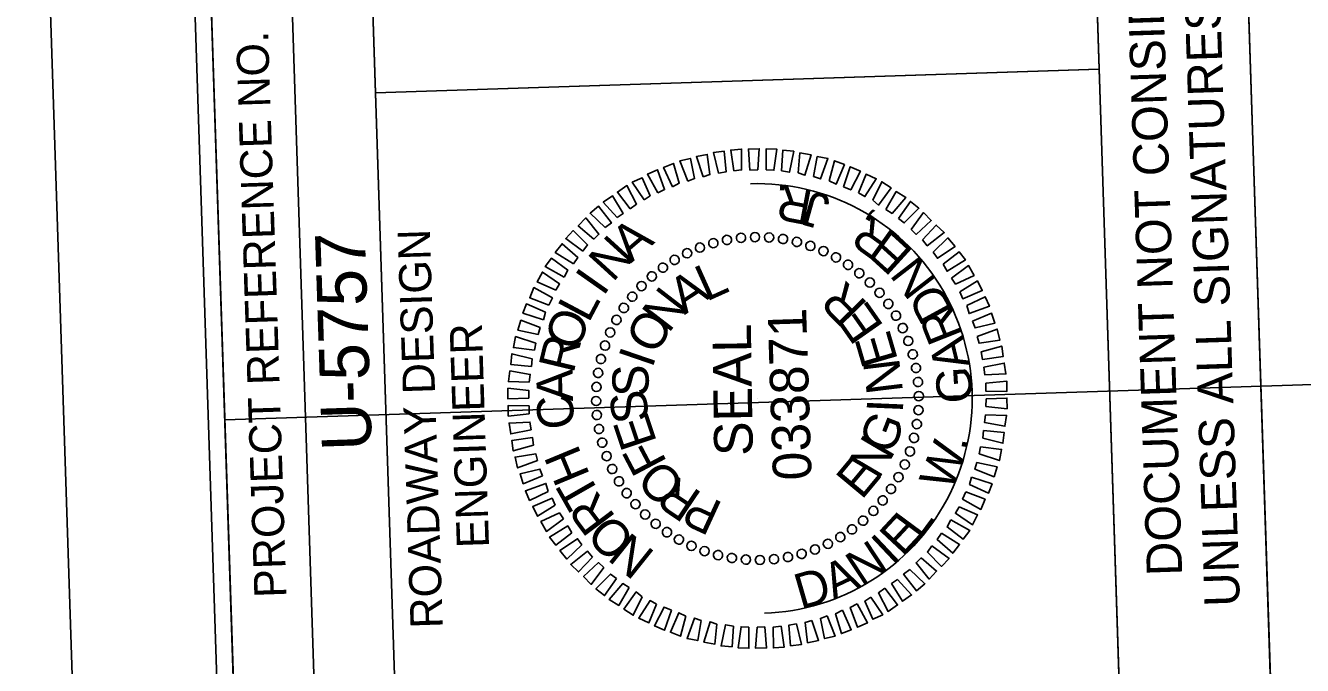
# Model space of a CAD drawing. Extents: x 1627314 to 1628469, y 762309 to 764212.
# Drawn here: x 1627314.2 to 1627512.6, y 763788.2 to 763887.6 of the extents above; entities that cross this region are included whole.
import ezdxf

# ---------------------------------------------------------------- set-up
doc = ezdxf.new("R2010")
doc.units = 0
for name, color, linetype in [('Old_Level_58', 7, 'Continuous'), ('Scratch_Level_0', 7, 'Continuous'), ('Sheet Data Field CELL', 7, 'Continuous'), ('Sheet Layout Profile Border Port 1', 7, 'Continuous'), ('Sheet Plot Border Inside CELL', 7, 'Continuous'), ('Sheet Plot Border Outside CELL', 7, 'Continuous'), ('Sheet Professional Seal CELL', 7, 'Continuous'), ('Sheet Profile CELL', 7, 'Continuous'), ('Sheet Profile Grid Major CELL', 7, 'Continuous'), ('Sheet Profile Grid Minor CELL', 7, 'Continuous'), ('Sheet Sticker Exception Certification CELL', 7, 'Continuous')]:
    doc.layers.add(name, color=color, linetype=linetype)

msp = doc.modelspace()

# ---------------------------------------------------------------- linework, layer by layer
at = {"layer": 'Old_Level_58'}
msp.add_lwpolyline([(1627507.79, 763781.55), (1627501.25, 763981.49), (1627565.16, 763983.58), (1627571.7, 763783.64)], close=True, dxfattribs=at)
at = {"layer": 'Scratch_Level_0'}
msp.add_arc((1627427.94, 763829.65), 33.36, 271.8735, 91.8735, dxfattribs=at)
at = {"layer": 'Sheet Layout Profile Border Port 1'}
msp.add_lwpolyline([(1627386.05, 762576.99), (1627885.78, 762593.33), (1627841.65, 763942.61), (1627566.8, 763933.62), (1627570.07, 763833.63), (1627345.19, 763826.32)], close=True, dxfattribs=at)
at = {"layer": 'Sheet Plot Border Inside CELL'}
msp.add_lwpolyline([(1628446.34, 762357.53), (1628391.86, 764023.14), (1627337.33, 763988.65), (1627391.81, 762323.04)], close=True, dxfattribs=at)
at = {"layer": 'Sheet Plot Border Outside CELL'}
msp.add_lwpolyline([(1628469.21, 762345.27), (1628413.63, 764044.37), (1627314.22, 764008.4), (1627369.79, 762309.31)], close=True, dxfattribs=at)
at = {"layer": 'Sheet Professional Seal CELL'}
for p, q in [((1627423.24, 763854.26), (1627423.24, 763854.26)), ((1627425.37, 763854.63), (1627425.37, 763854.63)), ((1627427.57, 763854.75), (1627427.57, 763854.75)), ((1627429.78, 763854.67), (1627429.78, 763854.67)), ((1627431.94, 763854.39), (1627431.94, 763854.39)), ((1627417, 763852.25), (1627417, 763852.25)), ((1627418.97, 763853.12), (1627418.97, 763853.12)), ((1627421.05, 763853.78), (1627421.05, 763853.78)), ((1627434.05, 763854.01), (1627434.05, 763854.01)), ((1627436.17, 763853.38), (1627436.17, 763853.38)), ((1627438.2, 763852.54), (1627438.2, 763852.54)), ((1627415.08, 763851.19), (1627415.08, 763851.19)), ((1627440.18, 763851.61), (1627440.18, 763851.61)), ((1627442.02, 763850.42), (1627442.02, 763850.42)), ((1627411.51, 763848.67), (1627411.51, 763848.67)), ((1627413.22, 763849.98), (1627413.22, 763849.98)), ((1627443.81, 763849.13), (1627443.81, 763849.13)), ((1627409.91, 763847.12), (1627409.91, 763847.12)), ((1627445.41, 763847.68), (1627445.41, 763847.68)), ((1627408.46, 763845.52), (1627408.46, 763845.52)), ((1627446.97, 763846.08), (1627446.97, 763846.08)), ((1627448.27, 763844.37), (1627448.27, 763844.37)), ((1627407.17, 763843.73), (1627407.17, 763843.73)), ((1627449.48, 763842.51), (1627449.48, 763842.51)), ((1627405.98, 763841.89), (1627405.98, 763841.89)), ((1627450.55, 763840.59), (1627450.55, 763840.59)), ((1627405.05, 763839.9), (1627405.05, 763839.9)), ((1627451.41, 763838.62), (1627451.41, 763838.62)), ((1627404.21, 763837.88), (1627404.21, 763837.88)), ((1627452.08, 763836.54), (1627452.08, 763836.54)), ((1627403.58, 763835.75), (1627403.58, 763835.75)), ((1627403.2, 763833.64), (1627403.2, 763833.64)), ((1627452.55, 763834.35), (1627452.55, 763834.35)), ((1627402.92, 763831.48), (1627402.92, 763831.48)), ((1627452.92, 763832.22), (1627452.92, 763832.22)), ((1627402.84, 763829.28), (1627402.84, 763829.28)), ((1627427.94, 763829.65), (1627427.94, 763829.65)), ((1627453.04, 763830.02), (1627453.04, 763830.02)), ((1627402.96, 763827.08), (1627402.96, 763827.08)), ((1627452.97, 763827.81), (1627452.97, 763827.81)), ((1627403.33, 763824.94), (1627403.33, 763824.94)), ((1627452.69, 763825.65), (1627452.69, 763825.65)), ((1627403.81, 763822.75), (1627403.81, 763822.75)), ((1627452.31, 763823.54), (1627452.31, 763823.54)), ((1627404.47, 763820.68), (1627404.47, 763820.68)), ((1627451.67, 763821.42), (1627451.67, 763821.42)), ((1627405.34, 763818.7), (1627405.34, 763818.7)), ((1627450.84, 763819.39), (1627450.84, 763819.39)), ((1627406.4, 763816.79), (1627406.4, 763816.79)), ((1627449.9, 763817.41), (1627449.9, 763817.41)), ((1627407.61, 763814.92), (1627407.61, 763814.92)), ((1627448.71, 763815.57), (1627448.71, 763815.57)), ((1627408.92, 763813.22), (1627408.92, 763813.22)), ((1627447.42, 763813.78), (1627447.42, 763813.78)), ((1627410.47, 763811.62), (1627410.47, 763811.62)), ((1627444.37, 763810.62), (1627444.37, 763810.62)), ((1627445.97, 763812.18), (1627445.97, 763812.18)), ((1627412.07, 763810.17), (1627412.07, 763810.17)), ((1627413.86, 763808.88), (1627413.86, 763808.88)), ((1627442.67, 763809.32), (1627442.67, 763809.32)), ((1627415.7, 763807.69), (1627415.7, 763807.69)), ((1627417.69, 763806.75), (1627417.69, 763806.75)), ((1627438.89, 763807.04), (1627438.89, 763807.04)), ((1627440.8, 763808.11), (1627440.8, 763808.11)), ((1627419.71, 763805.92), (1627419.71, 763805.92)), ((1627421.84, 763805.28), (1627421.84, 763805.28)), ((1627423.95, 763804.9), (1627423.95, 763804.9)), ((1627426.11, 763804.62), (1627426.11, 763804.62)), ((1627430.51, 763804.67), (1627430.51, 763804.67)), ((1627432.65, 763805.04), (1627432.65, 763805.04)), ((1627434.84, 763805.51), (1627434.84, 763805.51)), ((1627436.91, 763806.18), (1627436.91, 763806.18)), ((1627428.31, 763804.55), (1627428.31, 763804.55))]:
    msp.add_line(p, q, dxfattribs=at)
for points in [[(1627424.29, 763865), (1627423.78, 763868.23), (1627425.48, 763868.39), (1627425.48, 763865.14)], [(1627426.78, 763865.13), (1627426.53, 763868.37), (1627428.23, 763868.43), (1627427.98, 763865.17)], [(1627429.28, 763865.16), (1627429.28, 763868.41), (1627430.93, 763868.37), (1627430.49, 763865.1)], [(1627431.69, 763864.99), (1627431.88, 763868.2), (1627433.59, 763868.05), (1627432.9, 763864.78)], [(1627414.76, 763862.53), (1627413.36, 763865.54), (1627414.89, 763866.14), (1627415.79, 763863.07)], [(1627417.13, 763863.41), (1627415.88, 763866.57), (1627417.52, 763866.93), (1627418.17, 763863.8)], [(1627419.51, 763864.09), (1627418.46, 763867.21), (1627420.15, 763867.56), (1627420.55, 763864.42)], [(1627421.9, 763864.62), (1627421.09, 763867.84), (1627422.78, 763868.05), (1627423.09, 763864.86)], [(1627434.25, 763864.67), (1627434.55, 763867.78), (1627436.26, 763867.49), (1627435.31, 763864.31)], [(1627436.67, 763864.1), (1627437.22, 763867.22), (1627438.88, 763866.92), (1627437.73, 763863.74)], [(1627439.09, 763863.43), (1627439.89, 763866.56), (1627441.46, 763865.96), (1627440.16, 763862.91)], [(1627412.44, 763861.56), (1627410.85, 763864.46), (1627412.42, 763865.16), (1627413.52, 763862.09)], [(1627441.33, 763862.5), (1627442.37, 763865.64), (1627443.95, 763864.94), (1627442.44, 763862.04)], [(1627443.66, 763861.58), (1627444.81, 763864.47), (1627446.39, 763863.77), (1627444.63, 763861.01)], [(1627408.17, 763859.12), (1627406.18, 763861.7), (1627407.65, 763862.7), (1627409.15, 763859.85)], [(1627410.33, 763860.49), (1627408.48, 763863.23), (1627410.01, 763863.93), (1627411.26, 763861.12)], [(1627445.85, 763860.45), (1627447.25, 763863.3), (1627448.69, 763862.34), (1627446.77, 763859.68)], [(1627406.16, 763857.75), (1627403.98, 763860.13), (1627405.4, 763861.13), (1627407.09, 763858.38)], [(1627447.89, 763859.02), (1627449.5, 763861.77), (1627450.98, 763860.87), (1627448.86, 763858.4)], [(1627449.84, 763857.58), (1627451.71, 763860.24), (1627453.04, 763859.18), (1627450.76, 763856.91)], [(1627404.26, 763856.19), (1627401.94, 763858.41), (1627403.25, 763859.51), (1627405.24, 763856.92)], [(1627451.8, 763855.89), (1627453.76, 763858.51), (1627454.95, 763857.29), (1627452.62, 763855.12)], [(1627402.52, 763854.38), (1627400.1, 763856.45), (1627401.26, 763857.69), (1627403.3, 763855.16)], [(1627453.6, 763854.3), (1627455.73, 763856.57), (1627456.97, 763855.41), (1627454.33, 763853.37)], [(1627400.83, 763852.52), (1627398.16, 763854.49), (1627399.32, 763855.73), (1627401.55, 763853.5)], [(1627455.22, 763852.35), (1627457.54, 763854.58), (1627458.64, 763853.26), (1627455.9, 763851.42)], [(1627399.34, 763850.57), (1627396.53, 763852.33), (1627397.59, 763853.67), (1627400.01, 763851.55)], [(1627456.78, 763850.5), (1627459.26, 763852.43), (1627460.26, 763851.17), (1627457.41, 763849.42)], [(1627397.91, 763848.48), (1627394.96, 763850.13), (1627395.96, 763851.46), (1627398.47, 763849.59)], [(1627458.1, 763848.34), (1627460.74, 763850.28), (1627461.59, 763848.76), (1627458.73, 763847.41)], [(1627396.63, 763846.48), (1627393.73, 763847.74), (1627394.53, 763849.27), (1627397.19, 763847.45)], [(1627395.55, 763844.15), (1627392.56, 763845.3), (1627393.21, 763846.87), (1627396.07, 763845.26)], [(1627459.37, 763846.23), (1627462.11, 763847.92), (1627462.86, 763846.4), (1627459.85, 763845.15)], [(1627394.68, 763841.87), (1627391.49, 763842.91), (1627392.04, 763844.33), (1627394.99, 763843.03)], [(1627460.49, 763844.07), (1627463.34, 763845.46), (1627463.99, 763843.98), (1627460.83, 763842.83)], [(1627461.37, 763841.65), (1627464.33, 763842.89), (1627464.83, 763841.36), (1627461.75, 763840.61)], [(1627393.85, 763839.59), (1627390.73, 763840.24), (1627391.18, 763841.8), (1627394.17, 763840.65)], [(1627462.1, 763839.27), (1627465.21, 763840.42), (1627465.62, 763838.73), (1627462.38, 763838.23)], [(1627393.28, 763837.17), (1627390.01, 763837.56), (1627390.36, 763839.27), (1627393.49, 763838.23)], [(1627392.81, 763834.6), (1627389.6, 763834.95), (1627389.8, 763836.6), (1627392.92, 763835.81)], [(1627462.72, 763836.89), (1627465.9, 763837.79), (1627466.1, 763836.15), (1627462.91, 763835.69)], [(1627463.1, 763834.5), (1627466.28, 763835.15), (1627466.54, 763833.46), (1627463.29, 763833.3)], [(1627392.49, 763832.19), (1627389.24, 763832.28), (1627389.48, 763833.94), (1627392.65, 763833.4)], [(1627392.42, 763829.69), (1627389.17, 763829.58), (1627389.17, 763831.23), (1627392.43, 763830.89)], [(1627463.43, 763832.01), (1627466.67, 763832.36), (1627466.68, 763830.71), (1627463.42, 763830.81)], [(1627392.45, 763827.29), (1627389.21, 763826.93), (1627389.21, 763828.58), (1627392.46, 763828.49)], [(1627463.46, 763829.61), (1627466.71, 763829.71), (1627466.72, 763828.06), (1627463.45, 763828.41)], [(1627463.39, 763827.1), (1627466.65, 763827.01), (1627466.4, 763825.35), (1627463.23, 763825.9)], [(1627392.78, 763824.8), (1627389.6, 763824.14), (1627389.35, 763825.83), (1627392.59, 763825.99)], [(1627463.07, 763824.69), (1627466.29, 763824.35), (1627466.09, 763822.69), (1627462.96, 763823.49)], [(1627393.16, 763822.41), (1627389.99, 763821.5), (1627389.78, 763823.15), (1627392.97, 763823.6)], [(1627393.79, 763820.03), (1627390.68, 763818.87), (1627390.27, 763820.56), (1627393.5, 763821.07)], [(1627462.61, 763822.13), (1627465.87, 763821.73), (1627465.53, 763820.02), (1627462.39, 763821.07)], [(1627394.52, 763817.65), (1627391.56, 763816.4), (1627391.06, 763817.93), (1627394.13, 763818.69)], [(1627462.04, 763819.71), (1627465.16, 763819.06), (1627464.71, 763817.49), (1627461.72, 763818.65)], [(1627461.21, 763817.43), (1627464.4, 763816.38), (1627463.84, 763814.96), (1627460.9, 763816.27)], [(1627395.4, 763815.23), (1627392.54, 763813.83), (1627391.89, 763815.31), (1627395.06, 763816.46)], [(1627460.33, 763815.15), (1627463.32, 763814), (1627462.67, 763812.42), (1627459.82, 763814.03)], [(1627396.52, 763813.06), (1627393.77, 763811.37), (1627393.02, 763812.9), (1627396.03, 763814.15)], [(1627459.26, 763812.81), (1627462.15, 763811.56), (1627461.35, 763810.03), (1627458.69, 763811.84)], [(1627397.79, 763810.95), (1627395.15, 763809.01), (1627394.3, 763810.54), (1627397.16, 763811.88)], [(1627457.97, 763810.82), (1627460.93, 763809.16), (1627459.92, 763807.83), (1627457.41, 763809.7)], [(1627399.11, 763808.79), (1627396.62, 763806.86), (1627395.63, 763808.13), (1627398.47, 763809.87)], [(1627456.54, 763808.72), (1627459.35, 763806.96), (1627458.29, 763805.63), (1627455.87, 763807.75)], [(1627400.67, 763806.94), (1627398.34, 763804.72), (1627397.25, 763806.03), (1627399.99, 763807.87)], [(1627455.06, 763806.77), (1627457.72, 763804.81), (1627456.56, 763803.57), (1627454.34, 763805.8)], [(1627402.29, 763805), (1627400.16, 763802.72), (1627398.92, 763803.88), (1627401.55, 763805.92)], [(1627453.36, 763804.92), (1627455.78, 763802.84), (1627454.62, 763801.6), (1627452.59, 763804.14)], [(1627404.09, 763803.4), (1627402.12, 763800.79), (1627400.93, 763802), (1627403.26, 763804.18)], [(1627451.62, 763803.11), (1627453.95, 763800.88), (1627452.63, 763799.79), (1627450.65, 763802.37)], [(1627406.04, 763801.72), (1627404.18, 763799.05), (1627402.85, 763800.11), (1627405.12, 763802.39)], [(1627407.99, 763800.28), (1627406.38, 763797.53), (1627404.9, 763798.43), (1627407.02, 763800.9)], [(1627449.72, 763801.54), (1627451.9, 763799.16), (1627450.48, 763798.17), (1627448.79, 763800.91)], [(1627410.04, 763798.85), (1627408.63, 763796), (1627407.2, 763796.95), (1627409.11, 763799.62)], [(1627445.56, 763798.81), (1627447.4, 763796.07), (1627445.87, 763795.37), (1627444.63, 763798.18)], [(1627447.72, 763800.18), (1627449.7, 763797.59), (1627448.23, 763796.59), (1627446.74, 763799.45)], [(1627412.23, 763797.72), (1627411.07, 763794.83), (1627409.5, 763795.53), (1627411.26, 763798.28)], [(1627414.56, 763796.79), (1627413.51, 763793.66), (1627411.94, 763794.36), (1627413.44, 763797.26)], [(1627441.13, 763796.76), (1627442.52, 763793.75), (1627440.99, 763793.15), (1627440.09, 763796.23)], [(1627443.44, 763797.74), (1627445.04, 763794.84), (1627443.46, 763794.14), (1627442.36, 763797.2)], [(1627416.79, 763795.86), (1627415.99, 763792.74), (1627414.42, 763793.34), (1627415.72, 763796.38)], [(1627419.21, 763795.19), (1627418.67, 763792.07), (1627417.01, 763792.37), (1627418.15, 763795.56)], [(1627421.63, 763794.62), (1627421.34, 763791.51), (1627419.63, 763791.81), (1627420.57, 763794.99)], [(1627433.99, 763794.68), (1627434.8, 763791.45), (1627433.1, 763791.25), (1627432.8, 763794.44)], [(1627436.37, 763795.2), (1627437.43, 763792.09), (1627435.74, 763791.73), (1627435.33, 763794.87)], [(1627438.75, 763795.88), (1627440.01, 763792.72), (1627438.37, 763792.37), (1627437.71, 763795.5)], [(1627424.2, 763794.31), (1627424, 763791.1), (1627422.3, 763791.24), (1627422.99, 763794.52)], [(1627426.6, 763794.13), (1627426.61, 763790.88), (1627424.96, 763790.93), (1627425.4, 763794.2)], [(1627429.1, 763794.17), (1627429.36, 763790.92), (1627427.66, 763790.87), (1627427.9, 763794.13)], [(1627431.6, 763794.3), (1627432.11, 763791.06), (1627430.41, 763790.91), (1627430.4, 763794.16)]]:
    msp.add_lwpolyline(points, close=True, dxfattribs=at)
for centre, major_axis in [((1627421.08, 763853.77), (-0.197, 0.693)), ((1627423.21, 763854.28), (-0.136, 0.707)), ((1627425.38, 763854.6), (-0.074, 0.716)), ((1627427.56, 763854.72), (-0.011, 0.72)), ((1627429.75, 763854.66), (0.052, 0.718)), ((1627431.92, 763854.41), (0.114, 0.711)), ((1627434.06, 763853.97), (0.176, 0.698)), ((1627417, 763852.21), (-0.314, 0.648)), ((1627419.01, 763853.08), (-0.257, 0.673)), ((1627436.16, 763853.34), (0.236, 0.68)), ((1627438.19, 763852.54), (0.294, 0.657)), ((1627440.15, 763851.56), (0.35, 0.629)), ((1627413.25, 763849.97), (-0.422, 0.583)), ((1627415.07, 763851.17), (-0.369, 0.618)), ((1627442.01, 763850.41), (0.404, 0.596)), ((1627411.53, 763848.61), (-0.471, 0.544)), ((1627443.77, 763849.1), (0.454, 0.559)), ((1627445.4, 763847.65), (0.501, 0.517)), ((1627408.49, 763845.47), (-0.559, 0.454)), ((1627409.94, 763847.11), (-0.517, 0.501)), ((1627446.91, 763846.06), (0.544, 0.471)), ((1627407.18, 763843.72), (-0.596, 0.404)), ((1627448.27, 763844.34), (0.583, 0.422)), ((1627406.03, 763841.85), (-0.629, 0.35)), ((1627449.47, 763842.52), (0.618, 0.369)), ((1627405.05, 763839.9), (-0.657, 0.294)), ((1627450.51, 763840.59), (0.648, 0.314)), ((1627404.25, 763837.86), (-0.68, 0.236)), ((1627451.38, 763838.58), (0.673, 0.257)), ((1627403.62, 763835.77), (-0.698, 0.176)), ((1627452.07, 763836.51), (0.693, 0.197)), ((1627403.18, 763833.63), (-0.711, 0.114)), ((1627452.57, 763834.38), (0.707, 0.136)), ((1627452.89, 763832.21), (0.716, 0.074)), ((1627402.93, 763831.45), (-0.718, 0.052)), ((1627453.02, 763830.03), (0.72, 0.011)), ((1627402.87, 763829.26), (-0.72, -0.011)), ((1627452.96, 763827.84), (0.718, -0.052)), ((1627402.99, 763827.08), (-0.716, -0.074)), ((1627452.71, 763825.67), (0.711, -0.114)), ((1627403.31, 763824.92), (-0.707, -0.136)), ((1627403.82, 763822.79), (-0.693, -0.197)), ((1627452.26, 763823.53), (0.698, -0.176)), ((1627404.51, 763820.71), (-0.673, -0.257)), ((1627451.64, 763821.43), (0.68, -0.236)), ((1627405.38, 763818.7), (-0.648, -0.314)), ((1627450.83, 763819.4), (0.657, -0.294)), ((1627406.42, 763816.78), (-0.618, -0.369)), ((1627449.85, 763817.44), (0.629, -0.35)), ((1627407.62, 763814.95), (-0.583, -0.422)), ((1627447.4, 763813.82), (0.559, -0.454)), ((1627448.7, 763815.58), (0.596, -0.404)), ((1627408.98, 763813.24), (-0.544, -0.471)), ((1627445.95, 763812.19), (0.517, -0.501)), ((1627410.48, 763811.64), (-0.501, -0.517)), ((1627412.12, 763810.19), (-0.454, -0.559)), ((1627444.35, 763810.68), (0.471, -0.544)), ((1627413.87, 763808.89), (-0.404, -0.596)), ((1627440.81, 763808.12), (0.369, -0.618)), ((1627442.64, 763809.32), (0.422, -0.583)), ((1627415.74, 763807.74), (-0.35, -0.629)), ((1627417.69, 763806.76), (-0.294, -0.657)), ((1627419.73, 763805.95), (-0.236, -0.68)), ((1627436.88, 763806.21), (0.257, -0.673)), ((1627438.89, 763807.08), (0.314, -0.648)), ((1627421.82, 763805.33), (-0.176, -0.698)), ((1627423.96, 763804.88), (-0.114, -0.711)), ((1627426.14, 763804.63), (-0.052, -0.718)), ((1627428.33, 763804.57), (0.011, -0.72)), ((1627430.51, 763804.7), (0.074, -0.716)), ((1627432.67, 763805.02), (0.136, -0.707)), ((1627434.8, 763805.52), (0.197, -0.693))]:
    msp.add_ellipse(centre, major_axis=major_axis, ratio=0.999708, dxfattribs=at)
at = {"layer": 'Sheet Profile CELL'}
for p, q in [((1627359.37, 763776.71), (1627352.83, 763976.65)), ((1627368.59, 763877.11), (1627480.98, 763880.79))]:
    msp.add_line(p, q, dxfattribs=at)
for points in [[(1627340.28, 763976.24), (1627389.32, 762477.04), (1628438.76, 762511.37), (1628389.72, 764010.57)], [(1627368.59, 763877.11), (1627365.32, 763977.06), (1627477.76, 763980.74), (1627481.03, 763880.79)], [(1627346.82, 763776.3), (1627340.28, 763976.24), (1627365.32, 763977.06), (1627371.86, 763777.12)], [(1627371.86, 763777.12), (1627368.59, 763877.11), (1627481.03, 763880.79), (1627484.3, 763780.79)]]:
    msp.add_lwpolyline(points, close=True, dxfattribs=at)
at = {"layer": 'Sheet Profile Grid Major CELL'}
msp.add_lwpolyline([(1627861.27, 763342.93), (1627859.63, 763392.91), (1627359.9, 763376.56), (1627358.26, 763426.53), (1627858, 763442.88), (1627856.36, 763492.85), (1627356.63, 763476.51), (1627354.99, 763526.48), (1627854.73, 763542.83), (1627853.09, 763592.8), (1627353.36, 763576.45), (1627351.73, 763626.43), (1627851.46, 763642.77), (1627849.82, 763692.75), (1627350.09, 763676.4), (1627348.46, 763726.37), (1627848.19, 763742.72), (1627846.55, 763792.69), (1627346.82, 763776.35), (1627345.96, 763802.63)], dxfattribs=at)
at = {"layer": 'Sheet Sticker Exception Certification CELL'}
for p, q in [((1627501.25, 763981.49), (1627507.79, 763781.56)), ((1627501.25, 763981.49), (1627507.79, 763781.56)), ((1627484.3, 763780.79), (1627477.76, 763980.72)), ((1627484.3, 763780.79), (1627477.76, 763980.72))]:
    msp.add_line(p, q, dxfattribs=at)

# ---------------------------------------------------------------- texts
at = {"layer": 'Sheet Data Field CELL'}
msp.add_text('U-5757', height=7.75, rotation=91.8735, dxfattribs=at).set_placement((1627368.04, 763821.64))
at = {"layer": 'Sheet Professional Seal CELL'}
for s, height, rotation, p in [('A', 5.64, 40.4906, (1627408.3, 763850.62)), ('N', 5.64, 47.6924, (1627405.44, 763847.57)), ('L', 5.64, 24.2743, (1627420, 763844.65)), ('I', 5.64, 54.8936, (1627403.97, 763845.37)), ('A', 5.64, 33.6337, (1627416.61, 763842.58)), ('N', 5.64, 52.3501, (1627414.11, 763839.65)), ('R', 5.64, 134.3549, (1627445.22, 763844.32)), ('L', 5.64, 62.0943, (1627401.7, 763841.25)), ('E', 5.64, 124.9976, (1627447.69, 763840.85)), ('O', 5.64, 69.2946, (1627399.99, 763836.79)), ('O', 5.64, 61.707, (1627412.22, 763836.24)), ('SEAL', 5.998, 90.8735, (1627427.23, 763820.77)), ('R', 5.64, 76.4946, (1627399.35, 763833.41)), ('E', 5.64, 106.2852, (1627449.81, 763835.62)), ('I', 5.64, 71.0631, (1627411.58, 763834.21)), ('S', 5.64, 89.7739, (1627411.03, 763829.89)), ('N', 5.64, 96.9299, (1627450.57, 763830.69)), ('A', 5.64, 90.8938, (1627399.29, 763829.21)), ('S', 5.64, 99.1291, (1627411.19, 763826.3)), ('C', 5.64, 98.0933, (1627399.72, 763825.27)), ('I', 5.64, 87.5747, (1627450.53, 763827.33)), ('E', 5.64, 108.4845, (1627412.36, 763822.88)), ('G', 5.64, 68.8637, (1627448.85, 763820.73)), ('N', 5.64, 59.5074, (1627446.72, 763816.85)), ('H', 5.64, 112.4929, (1627401.97, 763817.74)), ('F', 5.64, 117.8405, (1627413.96, 763819.73)), ('E', 5.64, 50.1504, (1627444.12, 763813.77)), ('O', 5.64, 136.5547, (1627417.02, 763816.53)), ('T', 5.64, 119.6932, (1627403.72, 763814.55)), ('R', 5.64, 145.9131, (1627419.52, 763814.86)), ('R', 5.64, 126.894, (1627406.03, 763811.22)), ('P', 5.64, 155.2724, (1627422.77, 763813.37)), ('O', 5.64, 134.0952, (1627409.24, 763807.87)), ('N', 5.64, 141.297, (1627412.22, 763805.67))]:
    msp.add_text(s, height=height, rotation=rotation, dxfattribs=at).set_placement(p)
at = {"layer": 'Sheet Profile CELL'}
for s, height, p in [('PROJECT REFERENCE NO.', 5.0001, (1627354.78, 763798.78)), ('ROADWAY DESIGN', 5.0001, (1627379.05, 763794.02)), ('ENGINEER', 5, (1627386.24, 763806.51))]:
    msp.add_text(s, height=height, rotation=91.8735, dxfattribs=at).set_placement(p)
at = {"layer": 'Sheet Profile Grid Minor CELL'}
for s, height, rotation, p in [('R', 5.5, 169.2275, (1627436.79, 763861.93)), ('.', 5.5, 176.154, (1627432.84, 763862.76)), ('J', 5.5, 164.359, (1627439.5, 763861.06)), (',', 5.5, 151.1787, (1627446.36, 763857.59)), ('R', 5.5, 144.2523, (1627449.6, 763855.17)), ('E', 5.5, 137.6693, (1627452.38, 763852.52)), ('N', 5.5, 127.7376, (1627455.96, 763847.96)), ('D', 5.5, 118.5929, (1627458.51, 763843.28)), ('033871', 5.998, 91.8735, (1627436.37, 763817.02)), ('R', 5.5, 111.6665, (1627459.93, 763839.49)), ('A', 5.5, 103.4807, (1627461.01, 763834.84)), ('G', 5.5, 93.549, (1627461.41, 763829.06)), ('W', 5.5, 68.7626, (1627458.08, 763815.08)), ('.', 5.5, 80.3687, (1627460.39, 763821.44)), ('E', 5.5, 46.9243, (1627450.5, 763804.92)), ('L', 5.5, 53.5073, (1627453.18, 763807.66)), ('N', 5.5, 33.4721, (1627444.12, 763800.35)), ('I', 5.5, 43.4038, (1627448.93, 763803.58)), ('D', 5.5, 16.1417, (1627434.66, 763796.86)), ('A', 5.5, 25.2863, (1627439.79, 763798.34))]:
    msp.add_text(s, height=height, rotation=rotation, dxfattribs=at).set_placement(p)
at = {"layer": 'Sheet Sticker Exception Certification CELL'}
for s, p in [('UNLESS ALL SIGNATURES COMPLETED', (1627502.91, 763797.41)), ('UNLESS ALL SIGNATURES COMPLETED', (1627502.91, 763797.41)), ('DOCUMENT NOT CONSIDERED FINAL', (1627493.95, 763802.19)), ('DOCUMENT NOT CONSIDERED FINAL', (1627493.95, 763802.19))]:
    msp.add_text(s, height=5.5, rotation=91.8735, dxfattribs=at).set_placement(p)

doc.saveas('drawing.dxf')
